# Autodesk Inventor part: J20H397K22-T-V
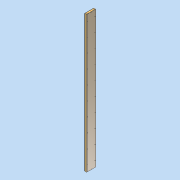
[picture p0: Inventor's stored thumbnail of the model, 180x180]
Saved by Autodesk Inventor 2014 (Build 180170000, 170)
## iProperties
Created: 2012-06
Part Number: J20H397K22-T-V
Document SubType Name: Modeling
Designer: david.appleford
Mass: 206875 g
Surface Area: 172265 cm^2
Volume: 206875 cm^3
Density: 1 g/cm^3
Description: Joist 5w x 400mm 22 Locks - 80mm
Cost Center: £400.00
Material: Generic
Appearance: Default
Justset: False
Author: david.appleford
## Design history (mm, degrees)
sketch "Sketch1"
  geometry: L1 (86, 0)-(86, 400); L2 (0, 400)-(0, 0); L3 (9.1, 356)-(76.9, 356); L4 (77, 400)-(77, 0); L5 (76.9, 44)-(9.1, 44); L6 (9, 0)-(9, 400); L7 (76.9, 355.9)-(9.1, 355.9); L8 (9.1, 44.1)-(76.9, 44.1); L9 (9.1, 400)-(9.1, 356); L10 (76.9, 356)-(76.9, 400); L11 (9.1, 355.9)-(9.1, 44.1); L12 (9.1, 44)-(9.1, 0); L13 (76.9, 0)-(76.9, 44); L14 (76.9, 44.1)-(76.9, 355.9); L15 (0, 0)-(9, 0); L16 (9.1, 0)-(76.9, 0); L17 (77, 0)-(86, 0); L18 (9, 400)-(0, 400); L19 (86, 400)-(77, 400); L20 (76.9, 400)-(9.1, 400)
  constraints: 40 end point, 22 parallel, 8 collinear, 7 perpendicular, 4 horizontal
  dimensions: "d1" = 86 distance between parallel lines of L1 L2; "d4" = 9 distance between parallel lines of L6 L2; "d5" = 9 distance between parallel lines of L1 L4; "d6" = 0.1 distance between parallel lines of L7 L3; "d7" = 0.1 distance between parallel lines of L9 L6; "d8" = 0.1 distance between parallel lines of L4 L10; "d9" = 0.1 distance between parallel lines of L5 L8; "d10" = 400 distance between parallel lines of L15 L18; "d11" = 44 distance between parallel lines of L3 L19; "d13" = 44 distance between parallel lines of L17 L5
extrude "Extrusion1" new body sketch "Sketch1" distance "d14" = 6032; taper "d15" = 0 deg
sketch "Sketch2" dims "d26" = 10
  geometry: L1 (0, 400)-(-6032, 400) reference; L2 (0, 0)-(-6032, 0) reference; L3 (34, 560.068)-(34, -205.63); L4 (-6066, 560.068)-(-6066, -205.63); L5 (0, 400)-(0, 0) reference; L6 (-6032, 400)-(-6032, 0) reference; 22 further points
  constraints: 4 end point, 1 horizontal, 1 horizontal alignment, 1 vertical alignment, 18 other
  dimensions: "d16" = 28 distance from line of L1 point (-271, 372); "d17" = 28 distance from line of L2 point (-271, 28) (= d16); "d18" = 34 distance between parallel lines of L5 L3; "d19" = 6100 distance between parallel lines of L4 L3; "d20" = 305 distance from line of point (-271, 372) L3; "d23" = 610 distance of point (-271, 372) point (-881, 372); "d35" = 28 distance from line of point (-6004, 200) L6 (= d16); "d36" = 28 distance from line of point (-28, 200) L5 (= d16); "d37" = 200 distance from line of point (-6004, 200) L1 (= 0.5 x d38); "d38" = 400 distance between parallel lines of L2 L1 (derived)
hole "Hole1" sketch "Sketch2" diameter "d28" = 13; stored, may be unused: countersink angle "d32" = 90 deg, drill point angle "d34" = 118 deg; dims "d29" = 6, "d30" = 4, "d31" = 2, "d33" = 20
body "Solid1"
other parameters: "d0" = 397, "d2" = 44, "d3" = 44
